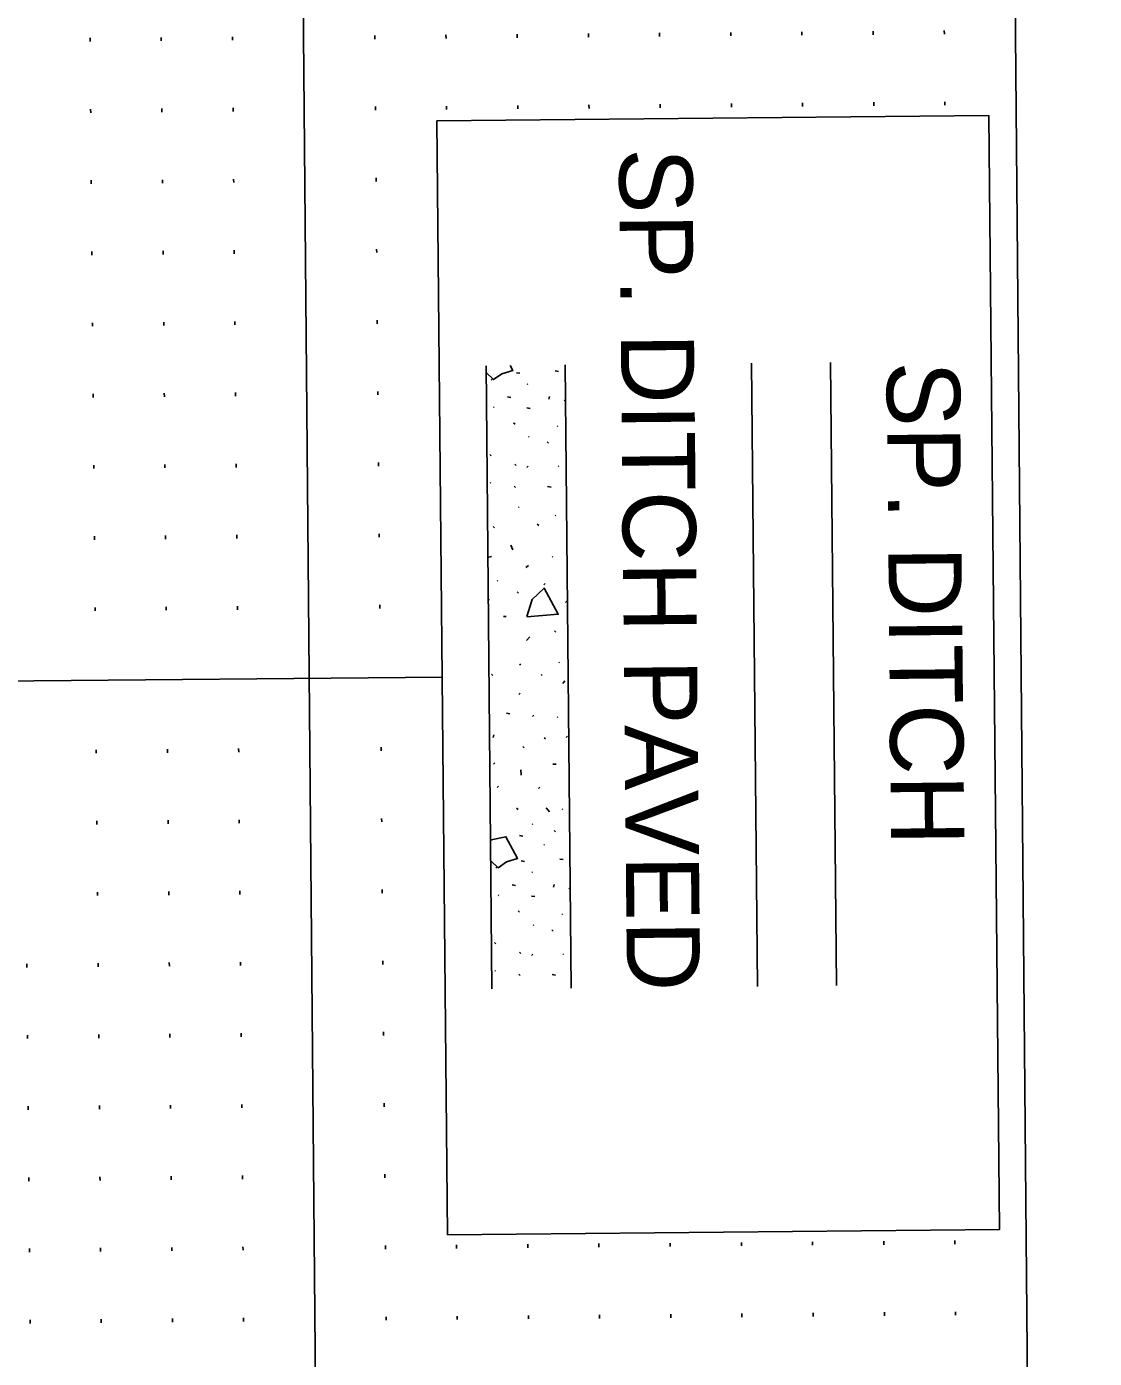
# Model space of a CAD drawing. Extents: x 2149873 to 2152007, y 140538 to 142349.
# Drawn here: x 2150414.5 to 2150489.5, y 141128.4 to 141221.9 of the extents above; entities that cross this region are included whole.
import ezdxf

# ---------------------------------------------------------------- set-up
doc = ezdxf.new("R2010")
doc.units = 0
for name, color, linetype in [('PR_Grading_Txt', 7, 'Continuous'), ('PR_Misc_Improvement', 7, 'Continuous'), ('PR_Storm_Ditch_Paved', 7, 'Continuous'), ('PR_Storm_Ditch_Special', 7, 'Continuous'), ('SHT_Profile_Grid_Major', 7, 'Continuous'), ('SHT_Profile_Grid_Minor', 7, 'Continuous'), ('SHT_Sheet_Border', 7, 'Continuous')]:
    doc.layers.add(name, color=color, linetype=linetype)

msp = doc.modelspace()

# ---------------------------------------------------------------- linework, layer by layer
at = {"layer": 'PR_Misc_Improvement'}
msp.add_lwpolyline([(2150482.086, 141215.655), (2150482.831, 141137.403), (2150444.07, 141137.034), (2150443.325, 141215.287)], close=True, dxfattribs=at)
at = {"layer": 'PR_Storm_Ditch_Paved'}
for p, q in [((2150447.226, 141197.151), (2150447.132, 141197.056)), ((2150449.146, 141197.545), (2150448.912, 141197.589)), ((2150451.865, 141197.666), (2150451.631, 141197.709)), ((2150449.715, 141196.754), (2150449.668, 141196.799)), ((2150448.505, 141195.851), (2150448.271, 141195.894)), ((2150451.225, 141195.922), (2150451.179, 141195.735)), ((2150452.259, 141195.652), (2150452.354, 141195.559)), ((2150447.338, 141195.137), (2150447.29, 141195.182)), ((2150449.873, 141195.066), (2150449.638, 141195.11)), ((2150446.837, 141193.725), (2150446.809, 141193.73)), ((2150448.709, 141194.071), (2150448.805, 141193.978)), ((2150451.808, 141193.819), (2150451.76, 141193.864)), ((2150449.798, 141193.048), (2150449.75, 141193.094)), ((2150451.068, 141192.733), (2150451.163, 141192.64)), ((2150447.042, 141191.851), (2150447.137, 141191.757)), ((2150448.784, 141191.163), (2150448.879, 141191.07)), ((2150449.724, 141191.031), (2150449.631, 141190.935)), ((2150451.882, 141191.005), (2150451.834, 141191.051)), ((2150447.107, 141189.833), (2150447.059, 141189.878)), ((2150448.752, 141189.614), (2150448.847, 141189.521)), ((2150451.333, 141189.546), (2150451.098, 141189.589)), ((2150449.095, 141188.117), (2150449.047, 141188.163)), ((2150450.371, 141186.957), (2150450.467, 141186.863)), ((2150451.679, 141187.532), (2150451.631, 141187.577)), ((2150447.277, 141186.786), (2150447.372, 141186.692)), ((2150448.51, 141185.483), (2150448.653, 141185.156)), ((2150447.157, 141184.673), (2150446.969, 141184.624)), ((2150449.743, 141184.04), (2150449.556, 141183.899)), ((2150451.472, 141184.621), (2150451.425, 141184.666)), ((2150447.595, 141182.943), (2150447.548, 141182.988)), ((2150448.962, 141182.206), (2150449.057, 141182.112)), ((2150450.928, 141182.786), (2150450.835, 141182.691)), ((2150446.997, 141181.668), (2150446.925, 141181.594)), ((2150452.44, 141181.532), (2150452.347, 141181.436)), ((2150448.182, 141180.461), (2150447.995, 141180.459)), ((2150451.569, 141179.462), (2150451.664, 141179.368)), ((2150449.606, 141178.786), (2150449.838, 141179.023)), ((2150449.152, 141177.139), (2150449.2, 141177.046)), ((2150451.918, 141177.214), (2150451.871, 141177.259)), ((2150447.142, 141176.418), (2150447.237, 141176.325)), ((2150450.706, 141176.372), (2150450.653, 141176.329)), ((2150452.306, 141175.95), (2150452.167, 141175.76)), ((2150449.172, 141175.076), (2150449.078, 141174.981)), ((2150448.435, 141173.616), (2150448.201, 141173.66)), ((2150450.125, 141173.535), (2150450.031, 141173.44)), ((2150451.814, 141173.367), (2150451.766, 141173.412)), ((2150447.324, 141172.15), (2150447.278, 141171.962)), ((2150450.843, 141171.95), (2150450.938, 141171.857)), ((2150452.483, 141172.057), (2150452.39, 141171.962)), ((2150449.347, 141171.326), (2150449.442, 141171.233)), ((2150447.388, 141170.18), (2150447.295, 141170.085)), ((2150451.705, 141170.08), (2150451.471, 141170.078)), ((2150449.226, 141169.306), (2150449.223, 141169.682)), ((2150447.639, 141168.54), (2150447.546, 141168.445)), ((2150450.547, 141168.473), (2150450.454, 141168.378)), ((2150448.92, 141167.006), (2150449.015, 141166.913)), ((2150451.221, 141166.745), (2150450.984, 141167.024)), ((2150452.157, 141166.895), (2150452.109, 141166.941)), ((2150450.057, 141165.844), (2150450.009, 141165.889)), ((2150451.562, 141165.437), (2150451.657, 141165.343)), ((2150449.361, 141165.04), (2150449.127, 141165.084)), ((2150450.867, 141164.397), (2150450.82, 141164.443)), ((2150452.191, 141163.381), (2150451.957, 141163.425)), ((2150447.552, 141162.867), (2150447.458, 141162.772)), ((2150449.472, 141163.261), (2150449.238, 141163.305)), ((2150450.041, 141162.469), (2150449.994, 141162.515)), ((2150448.831, 141161.566), (2150448.597, 141161.61)), ((2150451.551, 141161.638), (2150451.506, 141161.45)), ((2150447.664, 141160.852), (2150447.616, 141160.898)), ((2150450.199, 141160.782), (2150449.964, 141160.826)), ((2150452.585, 141161.368), (2150452.68, 141161.274)), ((2150449.036, 141159.787), (2150449.131, 141159.693)), ((2150447.163, 141159.44), (2150447.135, 141159.446)), ((2150450.124, 141158.764), (2150450.076, 141158.81)), ((2150452.134, 141159.535), (2150452.086, 141159.58)), ((2150451.394, 141158.449), (2150451.489, 141158.356)), ((2150447.368, 141157.567), (2150447.463, 141157.473)), ((2150449.11, 141156.879), (2150449.205, 141156.786)), ((2150450.05, 141156.746), (2150449.957, 141156.651)), ((2150452.208, 141156.721), (2150452.16, 141156.766)), ((2150447.433, 141155.549), (2150447.385, 141155.594)), ((2150449.078, 141155.33), (2150449.173, 141155.237)), ((2150451.659, 141155.262), (2150451.424, 141155.305))]:
    msp.add_line(p, q, dxfattribs=at)
for points in [[(2150446.773, 141197.594), (2150447.288, 141197.102), (2150447.877, 141197.512), (2150448.643, 141197.739), (2150448.455, 141198.096)], [(2150449.643, 141180.445), (2150451.84, 141180.622), (2150450.844, 141182.454), (2150450.018, 141181.66), (2150449.626, 141180.462)], [(2150448.783, 141163.812), (2150448.166, 141164.985), (2150447.129, 141164.768), (2150447.085, 141164.691)], [(2150447.099, 141163.31), (2150447.614, 141162.818), (2150448.203, 141163.228), (2150448.969, 141163.455), (2150448.782, 141163.812)]]:
    msp.add_lwpolyline(points, dxfattribs=at)
at = {"layer": 'PR_Storm_Ditch_Special'}
for p, q in [((2150446.768, 141198.08), (2150447.184, 141154.303)), ((2150452.33, 141198.133), (2150452.746, 141154.356)), ((2150465.41, 141198.257), (2150465.827, 141154.48)), ((2150470.972, 141198.31), (2150471.388, 141154.533))]:
    msp.add_line(p, q, dxfattribs=at)
at = {"layer": 'SHT_Profile_Grid_Major'}
for p, q in [((2150425.709, 142163.57), (2150439.495, 140588.63)), ((2149984.37, 141172.169), (2150443.703, 141176.19))]:
    msp.add_line(p, q, dxfattribs=at)
at = {"layer": 'SHT_Profile_Grid_Minor'}
for p, q in [((2150453.957, 141221.406), (2150453.96, 141221.156)), ((2150458.957, 141221.45), (2150458.959, 141221.2)), ((2150463.957, 141221.494), (2150463.959, 141221.244)), ((2150468.957, 141221.537), (2150468.959, 141221.287)), ((2150473.957, 141221.581), (2150473.959, 141221.331)), ((2150478.956, 141221.625), (2150478.959, 141221.375)), ((2150418.958, 141221.1), (2150418.96, 141220.85)), ((2150423.958, 141221.143), (2150423.96, 141220.894)), ((2150428.957, 141221.187), (2150428.96, 141220.937)), ((2150438.957, 141221.275), (2150438.959, 141221.025)), ((2150443.958, 141221.319), (2150443.96, 141221.069)), ((2150448.958, 141221.362), (2150448.96, 141221.112)), ((2150419.002, 141216.1), (2150419.004, 141215.85)), ((2150424.001, 141216.144), (2150424.004, 141215.894)), ((2150429.001, 141216.187), (2150429.003, 141215.937)), ((2150439.001, 141216.275), (2150439.003, 141216.025)), ((2150444.002, 141216.319), (2150444.004, 141216.069)), ((2150449.001, 141216.363), (2150449.004, 141216.113)), ((2150454.001, 141216.406), (2150454.003, 141216.156)), ((2150459.001, 141216.45), (2150459.003, 141216.2)), ((2150464.001, 141216.494), (2150464.003, 141216.244)), ((2150469.001, 141216.538), (2150469.003, 141216.288)), ((2150474, 141216.581), (2150474.003, 141216.331)), ((2150479, 141216.625), (2150479.002, 141216.375)), ((2150424.045, 141211.144), (2150424.047, 141210.894)), ((2150429.045, 141211.188), (2150429.047, 141210.938)), ((2150439.045, 141211.275), (2150439.047, 141211.025)), ((2150419.045, 141211.1), (2150419.048, 141210.85)), ((2150419.089, 141206.1), (2150419.091, 141205.85)), ((2150424.089, 141206.144), (2150424.091, 141205.894)), ((2150429.089, 141206.188), (2150429.091, 141205.938)), ((2150439.088, 141206.275), (2150439.091, 141206.025)), ((2150419.133, 141201.101), (2150419.135, 141200.851)), ((2150424.133, 141201.144), (2150424.135, 141200.894)), ((2150429.132, 141201.188), (2150429.135, 141200.938)), ((2150439.132, 141201.276), (2150439.134, 141201.026)), ((2150424.176, 141196.145), (2150424.179, 141195.895)), ((2150429.176, 141196.188), (2150429.178, 141195.938)), ((2150439.176, 141196.276), (2150439.178, 141196.026)), ((2150419.177, 141196.101), (2150419.179, 141195.851)), ((2150419.22, 141191.101), (2150419.223, 141190.851)), ((2150424.22, 141191.145), (2150424.222, 141190.895)), ((2150429.22, 141191.188), (2150429.222, 141190.938)), ((2150439.22, 141191.276), (2150439.222, 141191.026)), ((2150419.264, 141186.101), (2150419.266, 141185.851)), ((2150424.264, 141186.145), (2150424.266, 141185.895)), ((2150429.264, 141186.189), (2150429.266, 141185.939)), ((2150439.263, 141186.276), (2150439.266, 141186.026)), ((2150429.308, 141181.189), (2150429.31, 141180.939)), ((2150439.307, 141181.276), (2150439.309, 141181.026)), ((2150419.308, 141181.101), (2150419.31, 141180.851)), ((2150424.308, 141181.145), (2150424.31, 141180.895)), ((2150419.395, 141171.102), (2150419.398, 141170.852)), ((2150424.395, 141171.145), (2150424.397, 141170.895)), ((2150429.395, 141171.189), (2150429.397, 141170.939)), ((2150439.395, 141171.277), (2150439.397, 141171.027)), ((2150439.439, 141166.277), (2150439.441, 141166.027)), ((2150419.439, 141166.102), (2150419.441, 141165.852)), ((2150424.439, 141166.146), (2150424.441, 141165.896)), ((2150429.439, 141166.189), (2150429.441, 141165.939)), ((2150419.483, 141161.102), (2150419.485, 141160.852)), ((2150424.483, 141161.146), (2150424.485, 141160.896)), ((2150429.483, 141161.19), (2150429.485, 141160.94)), ((2150439.482, 141161.277), (2150439.484, 141161.027)), ((2150414.527, 141156.058), (2150414.529, 141155.808)), ((2150419.527, 141156.102), (2150419.529, 141155.852)), ((2150424.527, 141156.146), (2150424.529, 141155.896)), ((2150429.526, 141156.19), (2150429.529, 141155.94)), ((2150439.526, 141156.277), (2150439.528, 141156.027)), ((2150439.57, 141151.278), (2150439.572, 141151.028)), ((2150414.571, 141151.059), (2150414.573, 141150.809)), ((2150419.571, 141151.102), (2150419.573, 141150.852)), ((2150424.57, 141151.146), (2150424.573, 141150.896)), ((2150429.57, 141151.19), (2150429.572, 141150.94)), ((2150414.615, 141146.059), (2150414.617, 141145.809)), ((2150419.614, 141146.103), (2150419.616, 141145.853)), ((2150424.614, 141146.146), (2150424.616, 141145.896)), ((2150429.614, 141146.19), (2150429.616, 141145.94)), ((2150439.614, 141146.278), (2150439.616, 141146.028)), ((2150414.658, 141141.059), (2150414.66, 141140.809)), ((2150419.658, 141141.103), (2150419.66, 141140.853)), ((2150424.658, 141141.147), (2150424.66, 141140.897)), ((2150429.658, 141141.19), (2150429.66, 141140.94)), ((2150439.657, 141141.278), (2150439.66, 141141.028)), ((2150439.701, 141136.278), (2150439.703, 141136.028)), ((2150444.701, 141136.322), (2150444.703, 141136.072)), ((2150449.701, 141136.366), (2150449.703, 141136.116)), ((2150454.701, 141136.409), (2150454.703, 141136.159)), ((2150459.7, 141136.453), (2150459.703, 141136.203)), ((2150464.7, 141136.497), (2150464.702, 141136.247)), ((2150469.7, 141136.541), (2150469.702, 141136.291)), ((2150474.7, 141136.584), (2150474.702, 141136.334)), ((2150479.7, 141136.628), (2150479.702, 141136.378)), ((2150414.702, 141136.059), (2150414.704, 141135.809)), ((2150419.702, 141136.103), (2150419.704, 141135.853)), ((2150424.702, 141136.147), (2150424.704, 141135.897)), ((2150429.701, 141136.191), (2150429.704, 141135.941)), ((2150479.743, 141131.628), (2150479.745, 141131.378)), ((2150414.746, 141131.059), (2150414.748, 141130.81)), ((2150419.746, 141131.103), (2150419.748, 141130.853)), ((2150424.745, 141131.147), (2150424.748, 141130.897)), ((2150429.745, 141131.191), (2150429.747, 141130.941)), ((2150439.745, 141131.278), (2150439.747, 141131.028)), ((2150444.745, 141131.322), (2150444.747, 141131.072)), ((2150449.744, 141131.366), (2150449.747, 141131.116)), ((2150454.744, 141131.41), (2150454.746, 141131.16)), ((2150459.744, 141131.453), (2150459.746, 141131.203)), ((2150464.744, 141131.497), (2150464.746, 141131.247)), ((2150469.744, 141131.541), (2150469.746, 141131.291)), ((2150474.743, 141131.585), (2150474.746, 141131.335))]:
    msp.add_line(p, q, dxfattribs=at)
at = {"layer": 'SHT_Sheet_Border'}
msp.add_line((2150475.707, 142164.008), (2150489.493, 140589.068), dxfattribs=at)

# ---------------------------------------------------------------- texts
at = {"layer": 'PR_Grading_Txt'}
for s, height, p in [('SP. DITCH PAVED', 5.14286, (2150456.111, 141213.34)), ('SP. DITCH', 5.1429, (2150474.897, 141198.36))]:
    msp.add_text(s, height=height, rotation=270.54493, dxfattribs=at).set_placement(p)

doc.saveas('drawing.dxf')
